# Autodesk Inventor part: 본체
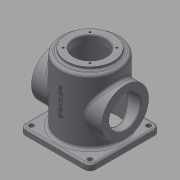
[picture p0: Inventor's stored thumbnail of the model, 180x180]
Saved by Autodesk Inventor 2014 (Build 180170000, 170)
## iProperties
Created: 2015-10
Part Number: 본체
Material: 일반
Document SubType Name: Modeling
Designer: USER
Density: 1 g/cm^3
Appearance: 기본값
Author: USER
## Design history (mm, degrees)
sketch "스케치1"
  geometry: L1 (0, 0)-(50, 0); L2 (50, 0)-(50, 110); L3 (50, 110)-(0, 110); L4 (0, 110)-(0, 0)
  constraints: 8 end point, 2 parallel, 1 horizontal, 1 perpendicular
  dimensions: "d1" = 100 diameter of L2 L4; "d2" = 110 distance of L1.end L2.end
revolve "회전1" sketch "스케치1" stored, may be unused: angle "d3" = 90 deg
sketch "스케치2"
  geometry: C1 r 50 at (0, 0) reference; C2 r 40 at (0, 0)
  constraints: 1 centre point, 1 coincident
  dimensions: "d4" = 80 diameter of C2
extrude "돌출1" join sketch "스케치2" distance "d5" = 5; taper "d6" = 0 deg
sketch "스케치3"
  geometry: L1 (-60, 0)-(60, 0); L2 (60, 0)-(60, -10); L3 (60, -10)-(-60, -10); L4 (-60, -10)-(-60, 0); 2 further points
  constraints: 8 end point, 2 midpoint, 2 parallel, 1 coincident, 1 horizontal, 1 perpendicular
  dimensions: "d7" = 10 distance of L1.end L2.end; "d8" = 120 distance of L2.end L3.end
extrude "돌출2" join sketch "스케치3" stored distance "d9" = 120; taper "d10" = 0 deg
fillet "모깎기1" dims "d11" = 10
fillet "모깎기2" dims "d12" = 3
hole "구멍1" diameter "d15" = 8; stored, may be unused: countersink angle "d19" = 90 deg, drill point angle "d21" = 118 deg; dims "d13" = 10, "d14" = 10, "d16" = 6, "d17" = 4, "d18" = 2, "d20" = 8
fillet "모깎기3" dims "d22" = 5
hole "구멍2" diameter "d25" = 54; stored, may be unused: countersink angle "d29" = 90 deg, drill point angle "d31" = 118 deg; dims "d23" = 10, "d24" = 10, "d26" = 6, "d27" = 4, "d28" = 2, "d30" = 8
hole "구멍3" diameter "d34" = 90; stored, may be unused: countersink angle "d38" = 90 deg, drill point angle "d40" = 0 deg; dims "d32" = 10, "d33" = 10, "d35" = 6, "d36" = 4, "d37" = 2, "d39" = 112
chamfer "모따기1" distance "d41" = 3; stored, may be unused: second distance "d42" = 2, angle "d43" = 45 deg
fillet "모깎기4" dims "d44" = 5
fillet "모깎기5" dims "d45" = 3
chamfer "모따기2" distance "d46" = 1; stored, may be unused: second distance "d47" = 2, angle "d48" = 45 deg
fillet "모깎기6" dims "d49" = 3
sketch "스케치4"
  geometry: L1 (-41.366, 41.366)-(0, 0); L2 (0, 0)-(-87.056, 0); C1 r 40 at (0, 0) reference; C2 r 28 at (0, 0) reference; 1 further point
  constraints: 4 end point, 1 horizontal, 1 point on line
  dimensions: "d50" = 45 deg angle of L2 L1; "d51" = 32.5 distance of C1.centre point (-22.981, 22.981)
hole "구멍4" sketch "스케치4" at (-22.981, 22.981) diameter "d52" = 3.242; stored, may be unused: countersink angle "d56" = 90 deg, drill point angle "d58" = 118 deg; dims "d53" = 8, "d54" = 4, "d55" = 2, "d57" = 10
node "작업 평면2"
  node "작업 평면1"
sketch "스케치5"
  geometry: L1 (-50, -65)-(50, -65) reference; L2 (40, 60)-(-40, 60) reference; 3 further points
  constraints: 1 midpoint, 1 vertical alignment, 1 other
  dimensions: "d63" = 70 distance from line of L1 point (0, 5)
feature "엠보싱1" sketch "스케치5" dims "d1" = 100, "d2" = 110, "d64" = 0.5, "d65" = 0
sketch "스케치6"
  geometry: L1 (-60, 90)-(60, 90); L2 (60, 90)-(60, 50); L3 (60, 50)-(-60, 50); L4 (-60, 50)-(-60, 90); L5 (60, -10)-(50, -10) reference; 2 further points
  constraints: 8 end point, 2 parallel, 1 horizontal, 1 midpoint, 1 perpendicular, 1 vertical alignment
  dimensions: "d66" = 60 distance from line of L5 L2.end; "d67" = 80 diameter of L1 L3; "d68" = 120 distance of L1.start L1.end
revolve "회전2" sketch "스케치6" stored, may be unused: angle "d69" = 90 deg
fillet "모깎기7" dims "d70" = 5
hole "구멍5" diameter "d73" = 54; stored, may be unused: countersink angle "d77" = 90 deg, drill point angle "d79" = 118 deg; dims "d71" = 10, "d72" = 10, "d74" = 8, "d75" = 4, "d76" = 2, "d78" = 10
chamfer "모따기3" distance "d80" = 1; stored, may be unused: second distance "d81" = 2, angle "d82" = 45 deg
hole "구멍6" diameter "d85" = 90; stored, may be unused: countersink angle "d89" = 90 deg, drill point angle "d91" = 0 deg; dims "d83" = 10, "d84" = 10, "d86" = 8, "d87" = 4, "d88" = 2, "d90" = 112
fillet "모깎기8" dims "d92" = 3
fillet "모깎기9" dims "d93" = 3
sketch "스케치7"
  geometry: C1 r 40 at (0, 0) reference; 2 further points
  constraints: 1 vertical alignment
  dimensions: "d94" = 32.5 distance of C1.centre point (0, 32.5)
hole "구멍7" sketch "스케치7" at (0, 32.5) diameter "d95" = 3.242; stored, may be unused: countersink angle "d99" = 90 deg, drill point angle "d101" = 118 deg; dims "d96" = 8, "d97" = 4, "d98" = 2, "d100" = 10
node "솔리드1"
mirror "대칭1"
mirror "대칭2"
pattern_circular "원형 패턴1" dims angle "d60" = 360 deg
pattern_circular "원형 패턴2" dims angle "d103" = 360 deg
mirror "대칭3"
other parameters: "d62" = 0.5
